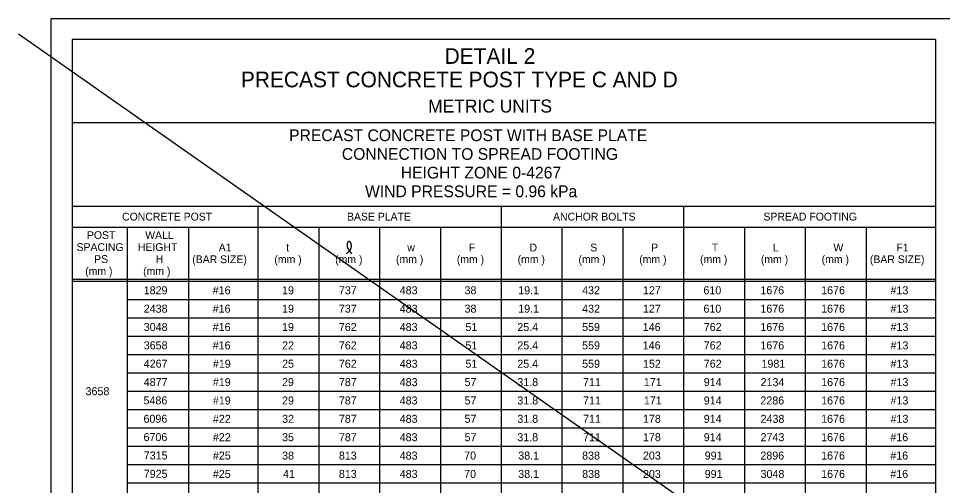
# Model space of a CAD drawing. Extents: x 3351 to 8430, y -3586 to 1457.
# Drawn here: x 7152.8 to 7507.3, y -810.5 to -631.3 of the extents above; entities that cross this region are included whole.
import ezdxf

# ---------------------------------------------------------------- set-up
doc = ezdxf.new("R2010")
doc.units = 0
doc.layers.add('1', color=7, linetype='Continuous')
doc.layers.add('2', color=7, linetype='Continuous')

msp = doc.modelspace()

# ---------------------------------------------------------------- linework, layer by layer
at = {"layer": '1'}
for p, q in [((7152.8, -637.24), (7925.95, -1178.57)), ((7173.34, -639.31), (7173.34, -985.5)), ((7504.68, -639.31), (7173.34, -639.31)), ((7504.68, -639.31), (7504.68, -985.5)), ((7504.68, -671.31), (7173.34, -671.31)), ((7173.34, -703.31), (7504.68, -703.31)), ((7173.34, -703.31), (7241.34, -703.31)), ((7173.34, -703.31), (7241.34, -703.31)), ((7173.34, -703.31), (7241.34, -703.31)), ((7244.68, -703.31), (7244.68, -985.5)), ((7338.01, -703.31), (7338.01, -985.5)), ((7408.01, -703.31), (7408.01, -985.5)), ((7173.34, -711.31), (7504.68, -711.31)), ((7194.68, -985.5), (7194.68, -711.31)), ((7218.01, -711.31), (7218.01, -985.5)), ((7268.01, -711.31), (7268.01, -985.5)), ((7291.34, -711.31), (7291.34, -985.5)), ((7314.68, -711.31), (7314.68, -985.5)), ((7361.34, -711.31), (7361.34, -985.5)), ((7384.68, -711.31), (7384.68, -985.5)), ((7431.34, -711.31), (7431.34, -985.5)), ((7454.68, -711.31), (7454.68, -985.5)), ((7478.01, -711.31), (7478.01, -985.5)), ((7173.34, -731.31), (7504.68, -731.31)), ((7173.34, -732.06), (7504.68, -732.06)), ((7231.33, -735.58), (7231.33, -735.58)), ((7256.34, -735.58), (7256.34, -735.58)), ((7279.68, -735.58), (7279.68, -735.58)), ((7303.01, -735.58), (7303.01, -735.58)), ((7326.34, -735.58), (7326.34, -735.58)), ((7349.68, -735.58), (7349.68, -735.58)), ((7373.01, -735.58), (7373.01, -735.58)), ((7396.34, -735.58), (7396.34, -735.58)), ((7419.67, -735.58), (7419.67, -735.58)), ((7443.01, -735.58), (7443.01, -735.58)), ((7466.34, -735.58), (7466.34, -735.58)), ((7491.33, -735.58), (7491.33, -735.58)), ((7194.68, -739.1), (7504.68, -739.1)), ((7194.68, -746.14), (7504.68, -746.14)), ((7194.68, -753.18), (7504.68, -753.18)), ((7194.68, -760.22), (7504.68, -760.22)), ((7194.68, -767.26), (7504.68, -767.26)), ((7194.68, -774.3), (7504.68, -774.3)), ((7194.68, -781.34), (7504.68, -781.34)), ((7194.68, -788.38), (7504.68, -788.38)), ((7194.68, -795.42), (7504.68, -795.42)), ((7194.68, -802.46), (7504.68, -802.46)), ((7194.68, -809.5), (7504.68, -809.5))]:
    msp.add_line(p, q, dxfattribs=at)
msp.add_spline([(7278.73, -721.48), (7278.94, -721.31), (7279.06, -721.18), (7279.26, -720.98), (7279.42, -720.82), (7279.7, -720.61), (7279.9, -720.35), (7280.08, -720.16), (7280.2, -719.93), (7280.3, -719.68), (7280.38, -719.44), (7280.46, -719.21), (7280.49, -719.02), (7280.52, -718.77), (7280.54, -718.55), (7280.52, -718.3), (7280.48, -718.05), (7280.43, -717.81), (7280.37, -717.58), (7280.28, -717.35), (7280.21, -717.22), (7280.11, -717.12), (7280.02, -717.02), (7279.92, -716.94), (7279.81, -716.88), (7279.72, -716.85), (7279.56, -716.85), (7279.46, -716.88), (7279.31, -716.93), (7279.22, -717.01), (7279.16, -717.1), (7279.09, -717.22), (7279.02, -717.33), (7278.98, -717.47), (7278.95, -717.58), (7278.91, -717.82), (7278.89, -717.99), (7278.91, -718.18), (7278.91, -718.38), (7278.95, -718.66), (7278.97, -718.89), (7279.01, -719.06), (7279.08, -719.28), (7279.18, -719.5), (7279.28, -719.7), (7279.37, -719.9), (7279.49, -720.12), (7279.69, -720.3), (7279.81, -720.51), (7279.94, -720.67), (7280.05, -720.85), (7280.2, -721.02), (7280.33, -721.19), (7280.44, -721.3), (7280.55, -721.43), (7280.66, -721.6)], degree=3, dxfattribs=at)
at = {"layer": '2'}
for p, q in [((7165.34, -1195.31), (7165.34, -631.31)), ((7165.34, -631.31), (7951.34, -631.31))]:
    msp.add_line(p, q, dxfattribs=at)

# ---------------------------------------------------------------- texts
at = {"layer": '1'}
for s, height, p in [('DETAIL 2', 6, (7316.31, -648.71)), ('PRECAST CONCRETE POST TYPE C AND D', 6, (7238.14, -657.71)), ('METRIC UNITS', 5, (7309.97, -667.41)), ('PRECAST CONCRETE POST WITH BASE PLATE', 4.5, (7256.63, -678.36)), ('CONNECTION TO SPREAD FOOTING', 4.5, (7276.86, -685.53)), ('HEIGHT ZONE 0-4267', 4.5, (7299.48, -692.69)), ('WIND PRESSURE = 0.96 kPa', 4.5, (7285.77, -699.86)), ('CONCRETE POST', 3, (7192.55, -708.81)), ('BASE PLATE', 3, (7278.84, -708.81)), ('ANCHOR BOLTS', 3, (7357.91, -708.81)), ('SPREAD FOOTING', 3, (7438.63, -708.81)), ('POST', 3, (7179.07, -715.91)), ('WALL', 3, (7201.42, -715.91)), ('SPACING', 3, (7175.07, -720.51)), ('HEIGHT', 3, (7198.59, -720.51)), ('A1', 3, (7229.64, -720.67)), ('t', 3, (7255.51, -720.67)), ('w', 3, (7301.99, -720.67)), ('F', 3, (7325.6, -720.67)), ('D', 3, (7348.87, -720.67)), ('S', 3, (7372.21, -720.67)), ('P', 3, (7395.54, -720.67)), ('T', 3, (7418.82, -720.67)), ('L', 3, (7442.27, -720.67)), ('W', 3, (7465.48, -720.67)), ('F1', 3, (7489.64, -720.67)), ('PS', 3, (7181.83, -725.11)), ('H', 3, (7205.47, -725.11)), ('(BAR SIZE)', 3, (7219.47, -725.17)), ('(mm )', 3, (7250.98, -725.17)), ('(mm )', 3, (7274.31, -725.17)), ('(mm )', 3, (7297.65, -725.17)), ('(mm )', 3, (7320.98, -725.17)), ('(mm )', 3, (7344.31, -725.17)), ('(mm )', 3, (7367.65, -725.17)), ('(mm )', 3, (7390.98, -725.17)), ('(mm )', 3, (7414.31, -725.17)), ('(mm )', 3, (7437.65, -725.17)), ('(mm )', 3, (7460.98, -725.17)), ('(BAR SIZE)', 3, (7479.47, -725.17)), ('(mm )', 3, (7178.4, -729.71)), ('(mm )', 3, (7200.63, -729.71)), ('1829', 3.07, (7200.84, -737.11)), ('#16', 3.07, (7227.31, -737.11)), ('19', 3.07, (7253.92, -737.11)), ('737', 3.07, (7275.73, -737.11)), ('483', 3.07, (7299.07, -737.11)), ('38', 3.07, (7323.94, -737.11)), ('19.1', 3.07, (7344.55, -737.11)), ('432', 3.07, (7369.07, -737.11)), ('127', 3.07, (7392.4, -737.11)), ('610', 3.07, (7415.6, -737.11)), ('1676', 3.07, (7437.45, -737.11)), ('1676', 3.07, (7460.78, -737.11)), ('#13', 3.07, (7487.39, -737.11)), ('2438', 3.07, (7200.86, -744.15)), ('#16', 3.07, (7227.31, -744.16)), ('19', 3.07, (7253.92, -744.16)), ('737', 3.07, (7275.73, -744.16)), ('483', 3.07, (7299.07, -744.16)), ('38', 3.07, (7323.94, -744.16)), ('19.1', 3.07, (7344.55, -744.16)), ('432', 3.07, (7369.07, -744.16)), ('127', 3.07, (7392.4, -744.16)), ('610', 3.07, (7415.6, -744.16)), ('1676', 3.07, (7437.45, -744.16)), ('1676', 3.07, (7460.78, -744.16)), ('#13', 3.07, (7487.39, -744.16)), ('3048', 3.07, (7200.86, -751.19)), ('#16', 3.07, (7227.31, -751.2)), ('19', 3.07, (7253.92, -751.2)), ('762', 3.07, (7275.73, -751.2)), ('483', 3.07, (7299.07, -751.2)), ('25.4', 3.07, (7344.2, -751.2)), ('559', 3.07, (7369.06, -751.2)), ('146', 3.07, (7392.32, -751.2)), ('762', 3.07, (7415.73, -751.2)), ('1676', 3.07, (7437.45, -751.2)), ('1676', 3.07, (7460.78, -751.2)), ('#13', 3.07, (7487.39, -751.2)), ('51', 3.07, (7324.29, -751.2)), ('3658', 3.07, (7200.86, -758.23)), ('#16', 3.07, (7227.31, -758.25)), ('22', 3.07, (7253.94, -758.25)), ('762', 3.07, (7275.73, -758.25)), ('483', 3.07, (7299.07, -758.25)), ('51', 3.07, (7324.29, -758.25)), ('25.4', 3.07, (7344.2, -758.25)), ('559', 3.07, (7369.06, -758.25)), ('146', 3.07, (7392.32, -758.25)), ('762', 3.07, (7415.73, -758.25)), ('1676', 3.07, (7437.45, -758.25)), ('1676', 3.07, (7460.78, -758.25)), ('#13', 3.07, (7487.39, -758.25)), ('4267', 3.07, (7200.86, -765.27)), ('#19', 3.07, (7227.38, -765.29)), ('25', 3.07, (7253.94, -765.29)), ('762', 3.07, (7275.73, -765.29)), ('483', 3.07, (7299.07, -765.29)), ('51', 3.07, (7324.29, -765.29)), ('25.4', 3.07, (7344.2, -765.29)), ('559', 3.07, (7369.06, -765.29)), ('152', 3.07, (7392.4, -765.29)), ('762', 3.07, (7415.73, -765.29)), ('1981', 3.07, (7437.88, -765.29)), ('1676', 3.07, (7460.78, -765.29)), ('#13', 3.07, (7487.39, -765.29)), ('4877', 3.07, (7200.86, -772.31)), ('#19', 3.07, (7227.38, -772.34)), ('29', 3.07, (7253.92, -772.34)), ('787', 3.07, (7275.73, -772.34)), ('483', 3.07, (7299.07, -772.34)), ('57', 3.07, (7323.94, -772.34)), ('31.8', 3.07, (7344.2, -772.34)), ('711', 3.07, (7369.42, -772.34)), ('171', 3.07, (7392.75, -772.34)), ('914', 3.07, (7415.73, -772.34)), ('2134', 3.07, (7437.53, -772.34)), ('1676', 3.07, (7460.78, -772.34)), ('#13', 3.07, (7487.39, -772.34)), ('3658', 3.07, (7178.53, -775.83)), ('5486', 3.07, (7200.77, -779.35)), ('#19', 3.07, (7227.38, -779.38)), ('29', 3.07, (7253.92, -779.38)), ('787', 3.07, (7275.73, -779.38)), ('483', 3.07, (7299.07, -779.38)), ('57', 3.07, (7323.94, -779.38)), ('31.8', 3.07, (7344.2, -779.38)), ('711', 3.07, (7369.42, -779.38)), ('171', 3.07, (7392.75, -779.38)), ('914', 3.07, (7415.73, -779.38)), ('2286', 3.07, (7437.45, -779.38)), ('1676', 3.07, (7460.78, -779.38)), ('#13', 3.07, (7487.39, -779.38)), ('6096', 3.07, (7200.77, -786.39)), ('#22', 3.07, (7227.39, -786.42)), ('32', 3.07, (7253.94, -786.42)), ('787', 3.07, (7275.73, -786.42)), ('483', 3.07, (7299.07, -786.42)), ('57', 3.07, (7323.94, -786.42)), ('31.8', 3.07, (7344.2, -786.42)), ('711', 3.07, (7369.42, -786.42)), ('178', 3.07, (7392.4, -786.42)), ('914', 3.07, (7415.73, -786.42)), ('2438', 3.07, (7437.53, -786.42)), ('1676', 3.07, (7460.78, -786.42)), ('#13', 3.07, (7487.39, -786.42)), ('6706', 3.07, (7200.77, -793.43)), ('#22', 3.07, (7227.39, -793.47)), ('35', 3.07, (7253.94, -793.47)), ('787', 3.07, (7275.73, -793.47)), ('483', 3.07, (7299.07, -793.47)), ('57', 3.07, (7323.94, -793.47)), ('31.8', 3.07, (7344.2, -793.47)), ('711', 3.07, (7369.42, -793.47)), ('178', 3.07, (7392.4, -793.47)), ('914', 3.07, (7415.73, -793.47)), ('2743', 3.07, (7437.53, -793.47)), ('1676', 3.07, (7460.78, -793.47)), ('#16', 3.07, (7487.31, -793.47)), ('7315', 3.07, (7200.86, -800.47)), ('#25', 3.07, (7227.39, -800.51)), ('38', 3.07, (7253.94, -800.51)), ('813', 3.07, (7275.73, -800.51)), ('483', 3.07, (7299.07, -800.51)), ('70', 3.07, (7323.8, -800.51)), ('38.1', 3.07, (7344.55, -800.51)), ('838', 3.07, (7369.07, -800.51)), ('203', 3.07, (7392.4, -800.51)), ('991', 3.07, (7416.09, -800.51)), ('2896', 3.07, (7437.45, -800.51)), ('1676', 3.07, (7460.78, -800.51)), ('#16', 3.07, (7487.31, -800.51)), ('7925', 3.07, (7200.86, -807.51)), ('#25', 3.07, (7227.39, -807.56)), ('41', 3.07, (7254.29, -807.56)), ('813', 3.07, (7275.73, -807.56)), ('483', 3.07, (7299.07, -807.56)), ('70', 3.07, (7323.8, -807.56)), ('38.1', 3.07, (7344.55, -807.56)), ('838', 3.07, (7369.07, -807.56)), ('203', 3.07, (7392.4, -807.56)), ('991', 3.07, (7416.09, -807.56)), ('3048', 3.07, (7437.53, -807.56)), ('1676', 3.07, (7460.78, -807.56)), ('#16', 3.07, (7487.31, -807.56))]:
    msp.add_text(s, height=height, dxfattribs=at).set_placement(p)

doc.saveas('drawing.dxf')
